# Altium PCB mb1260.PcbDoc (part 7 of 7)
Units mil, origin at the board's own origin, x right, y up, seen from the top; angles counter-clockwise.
Board outline 3189.01 x 3818.89 mil, 6 copper layers (TOP, L2_GND, L3_VCC, L4_SIG, L5_GND, BOTTOM), stack 62.2 mil thick; 308 components, 287 nets, 1220 pads, 851 vias.
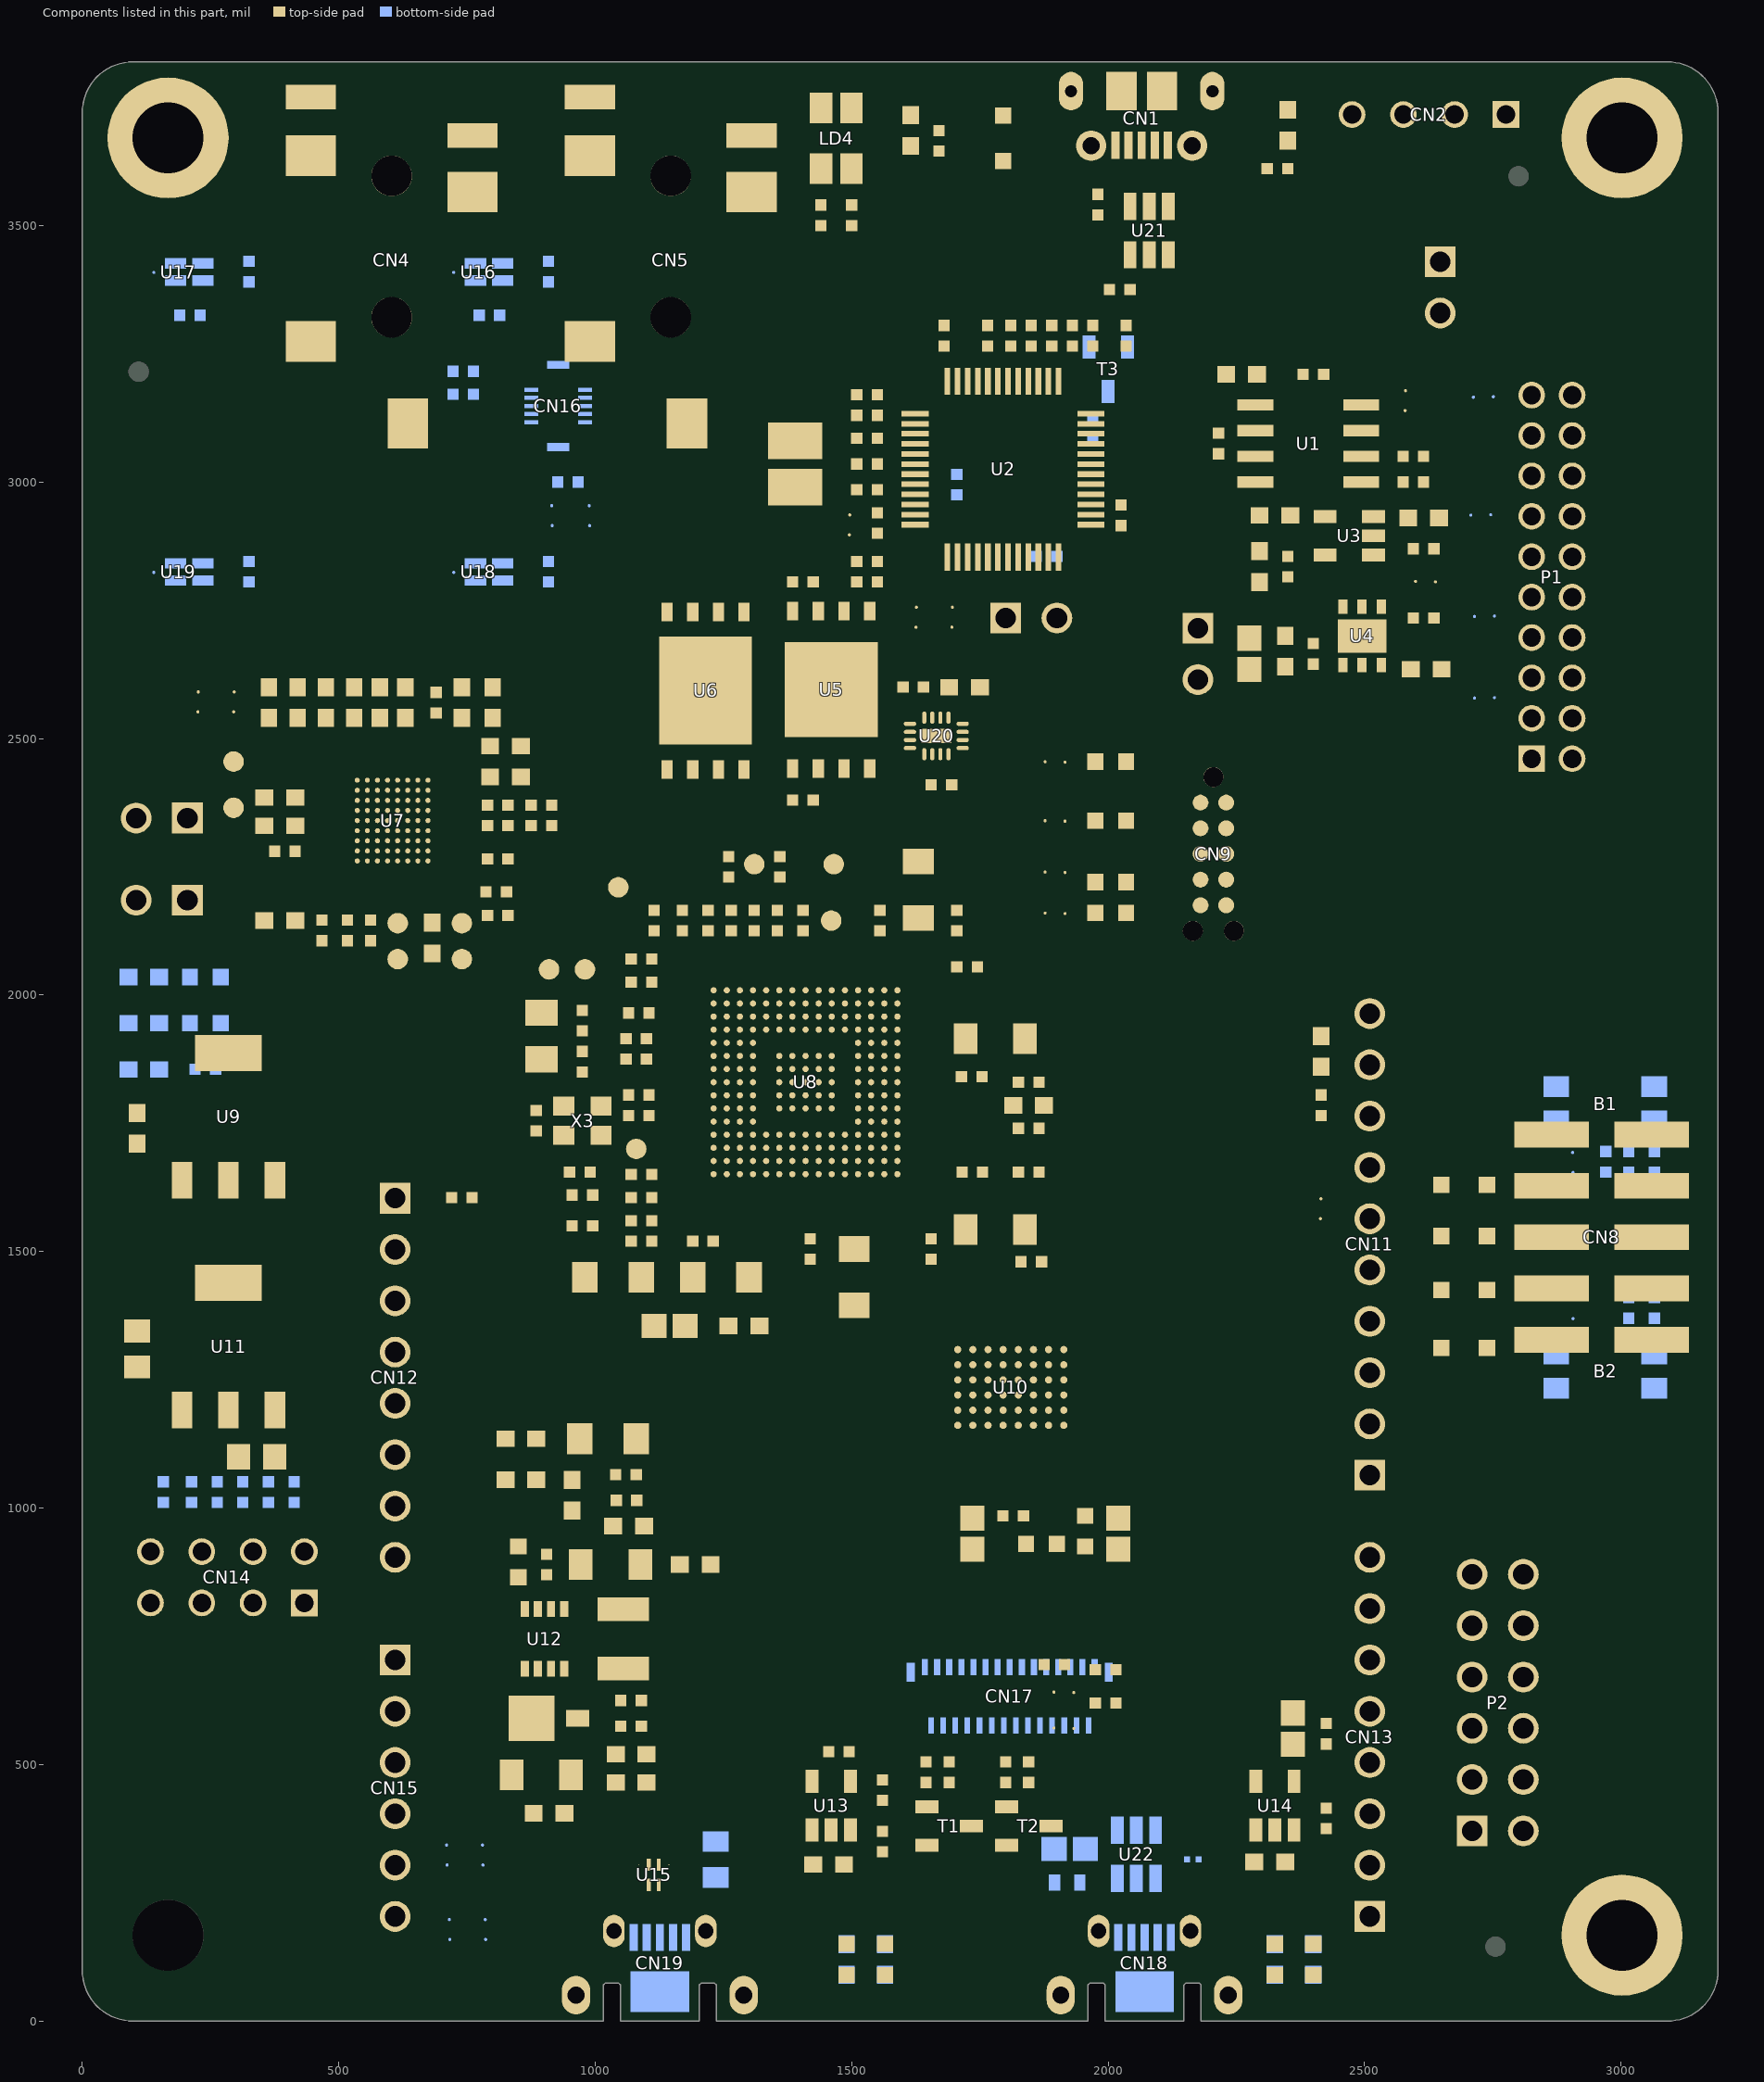
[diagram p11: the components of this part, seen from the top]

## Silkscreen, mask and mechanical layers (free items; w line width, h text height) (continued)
LAY13:
  text "13" at 2393.2,-1906.3 h75
  text "13" at 2393.2,-1906.3 h75
  text "LAYER 13(GND PLANE)" at 1943.2,-2056.3 h60
  text "LAYER 13(GND PLANE)" at 1943.2,-2056.3 h60
LAY11:
  text "11" at 2393.2,-1906.3 h75
  text "11" at 2393.2,-1906.3 h75
  text "LAYER 11(GND PLANE)" at 1943.2,-2056.3 h60
  text "LAYER 11(GND PLANE)" at 1943.2,-2056.3 h60
LAY6:
  text "6" at 2443.2,-1906.3 h75
  text "6" at 2443.2,-1906.3 h75
  text "LAYER 6 (GND PLANE)" at 1943.2,-2056.3 h60
  text "LAYER 6 (GND PLANE)" at 1943.2,-2056.3 h60
LAY12:
  text "12" at 2393.2,-1906.3 h75
  text "12" at 2393.2,-1906.3 h75
  text "LAYER 12(INTERNAL SIGNAL)" at 1943.2,-2056.3 h60
  text "LAYER 12(INTERNAL SIGNAL)" at 1943.2,-2056.3 h60
LAY8:
  text "8" at 2443.2,-1906.3 h75
  text "8" at 2443.2,-1906.3 h75
  text "LAYER 8 (GND PLANE)" at 1943.2,-2056.3 h60
  text "LAYER 8 (GND PLANE)" at 1943.2,-2056.3 h60
LAY17:
  text "17" at 2393.2,-1906.3 h75
  text "17" at 2393.2,-1906.3 h75
  text "LAYER 17(GND PLANE)" at 1943.2,-2056.3 h60
  text "LAYER 17(GND PLANE)" at 1943.2,-2056.3 h60
LAY15:
  text "15" at 2393.2,-1906.3 h75
  text "15" at 2393.2,-1906.3 h75
  text "LAYER 15(GND PLANE)" at 1943.2,-2056.3 h60
  text "LAYER 15(GND PLANE)" at 1943.2,-2056.3 h60
LAY9:
  text "9" at 2443.2,-1906.3 h75
  text "9" at 2443.2,-1906.3 h75
  text "LAYER 9 (INTERNAL SIGNAL)" at 1943.2,-2056.3 h60
  text "LAYER 9 (INTERNAL SIGNAL)" at 1943.2,-2056.3 h60
LAY14:
  text "14" at 2393.2,-1906.3 h75
  text "14" at 2393.2,-1906.3 h75
  text "LAYER 14(INTERNAL SIGNAL)" at 1943.2,-2056.3 h60
  text "LAYER 14(INTERNAL SIGNAL)" at 1943.2,-2056.3 h60
LAY16:
  text "16" at 2393.2,-1906.3 h75
  text "16" at 2393.2,-1906.3 h75
  text "LAYER 16(INTERNAL SIGNAL)" at 1943.2,-2056.3 h60
  text "LAYER 16(INTERNAL SIGNAL)" at 1943.2,-2056.3 h60
LAYER_COUNT:
  text "/XX" at 2393.2,-1906.3 h75
  text "/XX" at 2393.2,-1906.3 h75
ASSEMBLY_BOTTOM:
  lines w1: 896.6,3039.98 964.04,3039.98
  lines w5: -2316.97,2883.59 cw(c-2238.24,2883.59) -2238.23,2962.33 -1800.84,2962.33 ; -2316.97,2892.57 -2316.97,1361.55 ccw(c-2238.24,1361.55) -2238.23,1282.81 -1023.28,1282.81 ccw(c-1023.27,1361.55) -944.54,1361.55 -944.54,2883.59 ccw(c-1023.27,2883.59) -1023.28,2962.33 -1564.62,2962.33 ; 667.07,2539.58 cw(c745.81,2539.58) 745.81,2618.32 1960.77,2618.32 cw(c1960.77,2539.58) 2039.51,2539.58 2039.51,1017.54 cw(c1960.77,1017.54) 1960.77,938.8 745.81,938.8 cw(c745.81,1017.54) 667.07,1017.54 667.07,2548.56 ; 1183.21,2618.32 1183.21,2833.28 ; 1419.43,2618.32 1419.43,2833.28 ; 1628.72,938.56 1628.72,587.22 1983.05,587.22 1983.05,938.56 ; -1800.84,2962.33 -1564.62,2962.33 ; -1800.84,2962.33 -1800.84,3177.29 ; -1800.84,3177.29 -1564.62,3177.29 ; -1800.84,3177.29 -1899.26,3177.29 cw(c-1899.26,3196.98) -1918.95,3196.98 -1918.95,3364.3 ccw(c-1938.63,3364.31) -1938.63,3383.99 -2095.32,3383.99 cw(c-2095.32,3403.67) -2115.01,3403.67 -2115.01,3580.84 cw(c-2095.32,3580.84) -2095.32,3600.52 -1957.52,3600.52 cw(c-1957.53,3580.84) -1937.84,3580.84 -1937.84,3531.63 ccw(c-1918.16,3531.63) -1918.15,3511.94 -1466.19,3511.94 cw(c-1466.19,3492.26) -1446.51,3492.26 -1446.51,3196.98 cw(c-1466.19,3196.98) -1466.19,3177.29 -1564.62,3177.29 ; -1564.62,2962.33 -1564.62,3177.29 ; 1183.21,2833.28 1419.43,2833.28 ; 1183.21,2833.28 1084.79,2833.28 cw(c1084.79,2852.97) 1065.1,2852.97 1065.1,3020.29 ccw(c1045.41,3020.3) 1045.42,3039.98 888.72,3039.98 cw(c888.72,3059.66) 869.04,3059.66 869.04,3236.83 cw(c888.72,3236.83) 888.72,3256.51 1026.52,3256.51 cw(c1026.52,3236.83) 1046.2,3236.83 1046.2,3187.62 ccw(c1065.89,3187.61) 1065.89,3167.93 1517.86,3167.93 cw(c1517.85,3148.25) 1537.54,3148.25 1537.54,2852.97 cw(c1517.85,2852.97) 1517.86,2833.28 1419.43,2833.28 ; -2188.23,1584.77 -1073.28,1584.77 -1073.28,2699.74 -2188.23,2699.74 -2188.23,1584.77 ; -2173.99,3456.82 -2161,3456.82 -2161,3409.18 -2069.65,3409.18 -2069.65,3456.82 -2056.67,3456.82 -2056.67,3527.69 -2069.65,3527.69 -2069.65,3575.33 -2161,3575.33 -2161,3527.69 -2173.99,3527.69 -2173.99,3456.82 ; 751.32,1177.77 751.32,2418.72 2078.88,2418.72 2078.88,1177.77 751.32,1177.77 ; 795.81,1240.76 1910.77,1240.76 1910.77,2355.73 795.81,2355.73 795.81,1240.76 ; 810.06,3112.81 823.05,3112.81 823.05,3065.17 914.39,3065.17 914.39,3112.81 927.38,3112.81 927.38,3183.68 914.39,3183.68 914.39,3231.32 823.05,3231.32 823.05,3183.68 810.06,3183.68 810.06,3112.81
  text "Value" at -805.76,2172.57 h30 r90
  text "U888" at -1662.41,2122.57 h25 r90
  text "Value" at 2133.29,1773.56 h30 r90
  text "U*" at 1361.29,1768.56 h40 r90
  text "ASSEMBLY (SECONDARY)" at 3172.8,-2048.37 h60
  text "ASSEMBLY (SECONDARY)" at 3172.8,-2048.37 h60
ASSEMBLY_TOP:
  lines w5: 1236.36,2558.56 1236.36,2379.74 ; 1472.58,2558.56 1472.58,2379.74 ; 1236.36,2379.74 1472.58,2379.74 ; 1236.36,2379.74 1137.94,2379.74 ccw(c1137.94,2360.06) 1118.25,2360.06 1118.25,2192.73 cw(c1098.57,2192.74) 1098.57,2173.05 960.77,2173.05 ccw(c960.77,2153.37) 941.09,2153.36 941.09,1976.2 ccw(c960.77,1976.19) 960.77,1956.51 1098.57,1956.51 ccw(c1098.57,1976.2) 1118.25,1976.2 1118.25,2025.41 cw(c1137.94,2025.41) 1137.94,2045.1 1571.01,2045.1 ccw(c1571.01,2064.78) 1590.69,2064.78 1590.69,2360.06 ccw(c1571.01,2360.06) 1571.01,2379.74 1472.58,2379.74 ; -2119.74,2592.26 -2106.74,2592.26 -2106.74,2544.62 -2015.41,2544.62 -2015.41,2592.26 -2002.41,2592.26 -2002.41,2663.12 -2015.41,2663.12 -2015.41,2710.76 -2106.74,2710.76 -2106.74,2663.12 -2119.74,2663.12 -2119.74,2592.26 ; -2063.04,2539.11 ccw(c-2043.35,2539.1) -2043.36,2519.42 -1905.56,2519.42 ccw(c-1905.56,2539.11) -1885.88,2539.11 -1885.88,2588.32 cw(c-1866.19,2588.32) -1866.19,2608 -1414.21,2608 ccw(c-1414.22,2627.69) -1394.54,2627.69 -1394.54,2922.96 ccw(c-1414.22,2922.96) -1414.21,2942.65 -1847.3,2942.65 ccw(c-1847.29,2922.97) -1866.97,2922.96 -1866.97,2755.64 cw(c-1886.66,2755.64) -1886.67,2735.96 -2043.36,2735.96 ccw(c-2043.35,2716.27) -2063.04,2716.27 -2063.04,2539.11 ; 863.21,2029.35 876.2,2029.35 876.2,1981.71 967.54,1981.71 967.54,2029.35 980.53,2029.35 980.53,2100.21 967.54,2100.21 967.54,2147.85 876.2,2147.85 876.2,2100.21 863.21,2100.21 863.21,2029.35
  text "ASSEMBLY (PRIMARY)" at 1943.2,-2056.3 h60
  text "ASSEMBLY (PRIMARY)" at 1943.2,-2056.3 h60
LIB_UNEVALUATED:
  drawing of 273 lines, arcs and shapes, not listed
  text "4.5" at -2027.76,3675.57 h16 r90
  text "5.5" at -2147.76,3505.57 h16 r90
  text "16.21" at -2367.76,3282.57 h16 r90
  text "10.71" at -2147.76,3247.57 h16 r90
  text "16" at -1672.76,3199.57 h16 r90
  text "2" at -1277.76,3028.57 h16 r90
  text "12" at -1597.76,3024.57 h16 r90
  text "6" at -1232.76,3003.57 h16 r90
  text "10.71" at 916.29,2873.56 h16 r90
  text "8.5" at -1347.76,2785.57 h16 r90
  text "5.5" at -2352.76,2625.57 h16 r90
  text "1" at 2146.29,2544.56 h16 r90
  text "11.31" at 1011.29,2533.56 h16 r90
  text "33.72" at 1276.29,2498.56 h16 r90
  text "4.5" at -1972.76,2470.57 h16 r90
  text "28.32" at 1286.29,2308.56 h16 r90
  text "28.32" at -2397.76,2202.57 h16 r90
  text "LCD_CTP-LS015GF614A" at -973.76,2157.57 h30 r90
  text "42.66" at -2612.76,2097.57 h16 r90
  text "Sofer Lib Information" at 254.2,1980.35 h25 r90
  text "Sofer Lib Information" at 3583.16,1974.36 h25 r90
  text "Ref PN: FRD154BP2902-CTP" at 304.2,1950.35 h25 r90
  text "Creat : Ziv" at 344.2,1950.35 h25 r90
  text "Date  : 2016-05-28" at 384.2,1950.35 h25 r90
  text "Rev   : A1" at 424.2,1950.35 h25 r90
  text "Remark: D031-023A1" at 464.2,1950.35 h25 r90
  text "Ref PN: CTP LS015GF614A" at 3633.16,1944.36 h25 r90
  text "Creat : Yuki" at 3673.16,1944.36 h25 r90
  text "Date  : 2015-11-06" at 3713.16,1944.36 h25 r90
  text "Rev   : A1" at 3753.16,1944.36 h25 r90
  text "Remark: D031-015A2" at 3793.16,1944.36 h25 r90
  text "42.66" at 576.29,1783.56 h16 r90
  text "31.52" at 606.29,1783.56 h16 r90
  text "28.32" at 641.29,1783.56 h16 r90
  text "NO" at 1325.29,1778.56 h35 r90
  text "LCD_FRD154BP2902-CTP" at 1953.29,1758.56 h30 r90
  text "7.67" at -2397.76,1431.57 h16 r90
  text "28.32" at -1677.76,1237.57 h16 r90
  text "34.86" at -1677.76,1167.57 h16 r90
  text "15" at 1577.31,875.56 h16 r90
  text "9" at 1812.31,569.56 h16 r90
  text "MUTI-PACK DRAWING" at 1943.2,-2056.3 h60
  text "MUTI-PACK DRAWING" at 1943.2,-2056.3 h60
